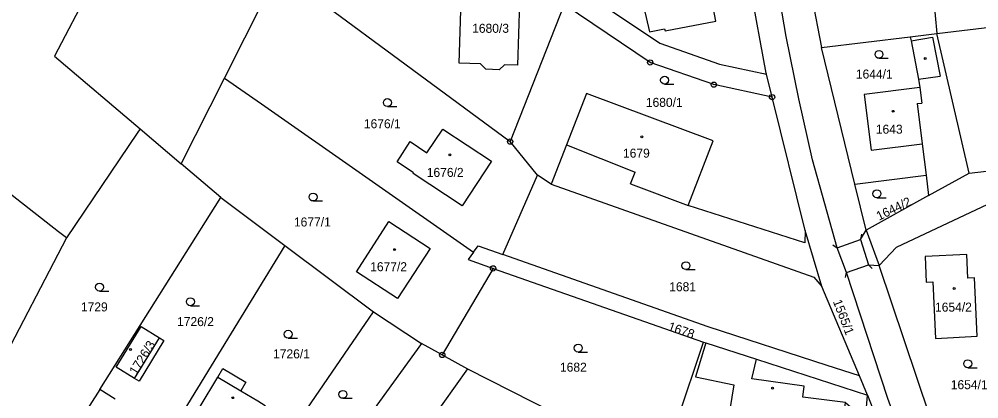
# Model space of a CAD drawing. Extents: x -562167 to -556918, y -1077891 to -1070763.
# Drawn here: x -560210.1 to -560029.1, y -1075940.9 to -1075869.3 of the extents above; entities that cross this region are included whole.
import ezdxf

# ---------------------------------------------------------------- set-up
doc = ezdxf.new("R2010")
doc.units = 0
for name, color, linetype in [('Hranice parcel', 7, 'Continuous'), ('Parcelní čísla', 7, 'Continuous'), ('Vnitřní kresba', 7, 'Continuous'), ('Značky bodu BP', 7, 'Continuous'), ('Značky budov', 7, 'Continuous'), ('Značky kultur', 7, 'Continuous')]:
    doc.layers.add(name, color=color, linetype=linetype)

msp = doc.modelspace()

# ---------------------------------------------------------------- linework, layer by layer
at = {"layer": 'Hranice parcel'}
for p, q in [((-560038.94, -1075850.52), (-560037.03, -1075871.93)), ((-560062.57, -1075854.97), (-560058.8, -1075874.61)), ((-560171.4, -1075880.35), (-560161.16, -1075860.03)), ((-560155.41, -1075864.37), (-560117.51, -1075892.34)), ((-560037.03, -1075871.93), (-560014.56, -1075869.3)), ((-560058.8, -1075874.61), (-560042.05, -1075872.55)), ((-560042.05, -1075872.55), (-560037.03, -1075871.93)), ((-560030.93, -1075898.29), (-560037.03, -1075871.93)), ((-560052.49, -1075900.39), (-560058.8, -1075874.61)), ((-560068.11, -1075883.95), (-560069.18, -1075879.62)), ((-560179.57, -1075896.55), (-560171.4, -1075880.35)), ((-560061.89, -1075909.1), (-560068.11, -1075883.95)), ((-560187.34, -1075889.94), (-560179.57, -1075896.55)), ((-560112.35, -1075898.64), (-560117.51, -1075892.34)), ((-560030.93, -1075898.29), (-560009.6, -1075895.89)), ((-560172.11, -1075902.9), (-560179.57, -1075896.55)), ((-560118.89, -1075913.64), (-560112.35, -1075898.64)), ((-560109.77, -1075900.37), (-560112.35, -1075898.64)), ((-560052.49, -1075900.39), (-560039.05, -1075898.65)), ((-560039.05, -1075898.65), (-560038.56, -1075902.52)), ((-560038.56, -1075902.52), (-560030.93, -1075898.29)), ((-560050.37, -1075909.07), (-560052.49, -1075900.39)), ((-560194.96, -1075939.09), (-560172.11, -1075902.9)), ((-560172.11, -1075902.9), (-560160.01, -1075911.93)), ((-560038.56, -1075902.52), (-560050.37, -1075909.07)), ((-560201.24, -1075910.47), (-560216.83, -1075940.47)), ((-560058.7, -1075919.66), (-560061.89, -1075909.1)), ((-560050.37, -1075909.07), (-560047.88, -1075915.74)), ((-560160.01, -1075911.93), (-560181.72, -1075947.3)), ((-560160.01, -1075911.93), (-560143.27, -1075924.43)), ((-560054.09, -1075917.01), (-560055.8, -1075912.37)), ((-560080.13, -1075927.3), (-560118.89, -1075913.64)), ((-560038.33, -1075944.12), (-560047.88, -1075915.74)), ((-560120.74, -1075916.25), (-560130.33, -1075932.58)), ((-560120.74, -1075916.25), (-560081.06, -1075930.15)), ((-560051.64, -1075936.52), (-560058.7, -1075919.66)), ((-560163.86, -1075954.36), (-560143.27, -1075924.43)), ((-560143.27, -1075924.43), (-560134.24, -1075930.44)), ((-560134.24, -1075930.44), (-560153.94, -1075957.49)), ((-560130.33, -1075932.58), (-560134.24, -1075930.44)), ((-560088.25, -1075951.75), (-560081.06, -1075930.15)), ((-560081.06, -1075930.15), (-560080.62, -1075930.29)), ((-560130.33, -1075932.58), (-560125.55, -1075935.2)), ((-560125.55, -1075935.2), (-560147.67, -1075966.13)), ((-560125.55, -1075935.2), (-560109.21, -1075943.5)), ((-560050.11, -1075940.17), (-560051.64, -1075936.52)), ((-560194.96, -1075939.09), (-560201.73, -1075949.81)), ((-560192.06, -1075940.89), (-560194.96, -1075939.09)), ((-560050.47, -1075944.82), (-560050.11, -1075940.17)), ((-560050.11, -1075940.17), (-560037.82, -1075971.43))]:
    msp.add_line(p, q, dxfattribs=at)
for points in [[(-560055.8, -1075912.37), (-560060.46, -1075895.76), (-560063.07, -1075884.26), (-560065.43, -1075872.49), (-560069.44, -1075848.98), (-560072.17, -1075831.75), (-560073.93, -1075817.46), (-560074.34, -1075808.46), (-560074.45, -1075801.18), (-560074.17, -1075792.89), (-560072.93, -1075783.94), (-560071.76, -1075777.87), (-560070.38, -1075772.61), (-560068.31, -1075767.18), (-560065.69, -1075762.57)], [(-560069.18, -1075879.62), (-560069.22, -1075879.43), (-560075.13, -1075847.2)], [(-560081.17, -1075856.82), (-560090.97, -1075858.65), (-560090.56, -1075860.6), (-560093.6, -1075861.3), (-560091.2, -1075871.65), (-560088.37, -1075871.05), (-560088.28, -1075871.44), (-560078.72, -1075869.61), (-560081.17, -1075856.82)], [(-560123.09, -1075877.68), (-560127.12, -1075877.55), (-560126.66, -1075861.57), (-560115.13, -1075861.9), (-560115.25, -1075866.12), (-560115.75, -1075866.1), (-560116.11, -1075877.91), (-560118.59, -1075877.83), (-560119.61, -1075878.8), (-560122.13, -1075878.7), (-560123.09, -1075877.68)], [(-560108.49, -1075860.9), (-560089.3, -1075873.8), (-560078.02, -1075877.75), (-560069.18, -1075879.62)], [(-560196.78, -1075863.31), (-560203.48, -1075876.2), (-560187.34, -1075889.94)], [(-560068.11, -1075883.95), (-560079.09, -1075881.6), (-560091.1, -1075877.41), (-560107.34, -1075866.47), (-560117.51, -1075892.34)], [(-560042.05, -1075872.55), (-560041.89, -1075873.36), (-560040.48, -1075880.57), (-560040.23, -1075882.16), (-560050.7, -1075883.43), (-560049.43, -1075893.93), (-560039.8, -1075892.76), (-560039.05, -1075898.65)], [(-560171.4, -1075880.35), (-560164.43, -1075885.2), (-560124.46, -1075913.2)], [(-560061.89, -1075909.1), (-560061.94, -1075911.44), (-560083.92, -1075904.4), (-560079.19, -1075892.18), (-560103.09, -1075883.29), (-560106.86, -1075892.92), (-560109.77, -1075900.37)], [(-560187.34, -1075889.94), (-560187.91, -1075890.78), (-560201.24, -1075910.47)], [(-560121.04, -1075896.04), (-560126.58, -1075904.47), (-560135.84, -1075898.38), (-560135.73, -1075898.21), (-560138.81, -1075896.15), (-560136.37, -1075892.35), (-560133.22, -1075894.47), (-560130.22, -1075890.02), (-560121.04, -1075896.04)], [(-560201.24, -1075910.47), (-560202.7, -1075909.33), (-560224.91, -1075892)], [(-560109.77, -1075900.37), (-560060.23, -1075917.93), (-560058.7, -1075919.66)], [(-560047.88, -1075915.74), (-560044.64, -1075912.25), (-560026.31, -1075903.66)], [(-560140.38, -1075907.43), (-560132.62, -1075912.49), (-560138.76, -1075921.91), (-560146.49, -1075916.9), (-560140.38, -1075907.43)], [(-560124.46, -1075913.2), (-560123.58, -1075911.98), (-560118.89, -1075913.64)], [(-560124.46, -1075913.2), (-560125.46, -1075914.6), (-560120.74, -1075916.25)], [(-560031.39, -1075913.61), (-560039.24, -1075914.03), (-560039.04, -1075918.85), (-560037.76, -1075918.8), (-560037.3, -1075929.47), (-560029.44, -1075929.03), (-560029.94, -1075918.01), (-560031.17, -1075918.09), (-560031.39, -1075913.61)], [(-560034.28, -1076097.89), (-560030.13, -1076040.04), (-560029.83, -1076034), (-560029.98, -1076027.95), (-560033.68, -1075983.37), (-560034.44, -1075977.55), (-560036.67, -1075967.75), (-560038.58, -1075961.71), (-560046.27, -1075940.8), (-560054.09, -1075917.01)], [(-560183.69, -1075929.36), (-560182.84, -1075929.86), (-560187.53, -1075937.5), (-560188.36, -1075937), (-560191.85, -1075934.91), (-560187.16, -1075927.21), (-560183.69, -1075929.36)], [(-560051.64, -1075936.52), (-560057.69, -1075934.56), (-560080.13, -1075927.3)], [(-560080.62, -1075930.29), (-560082.56, -1075936.71), (-560075.34, -1075938.19), (-560076.08, -1075942.89), (-560062.76, -1075944.73), (-560063.29, -1075949.12), (-560055.25, -1075950.14), (-560054.22, -1075941.55), (-560050.47, -1075944.82)], [(-560080.62, -1075930.29), (-560071.07, -1075933.38), (-560050.11, -1075940.17)], [(-560172.69, -1075936.75), (-560171.7, -1075935.15), (-560167.4, -1075937.73), (-560168.36, -1075939.32), (-560165.12, -1075941.24), (-560163.74, -1075942.1), (-560167.02, -1075947.62), (-560168.41, -1075946.79), (-560170.15, -1075949.83), (-560177.78, -1075945.28), (-560176.01, -1075942.31), (-560172.69, -1075936.75)]]:
    msp.add_lwpolyline(points, dxfattribs=at)
at = {"layer": 'Vnitřní kresba'}
for p, q in [((-560041.89, -1075873.36), (-560037.82, -1075872.65)), ((-560037.82, -1075872.65), (-560036.42, -1075879.97)), ((-560040.48, -1075880.57), (-560036.42, -1075879.97)), ((-560040.23, -1075882.16), (-560039.88, -1075885.06)), ((-560040.76, -1075885.17), (-560039.88, -1075885.06)), ((-560040.76, -1075885.17), (-560039.8, -1075892.76)), ((-560106.86, -1075892.92), (-560093.96, -1075898.11)), ((-560094.79, -1075900.32), (-560093.96, -1075898.11)), ((-560094.79, -1075900.32), (-560083.92, -1075904.4)), ((-560051.4, -1075910.78), (-560050.37, -1075909.07)), ((-560051.21, -1075909.8), (-560051.4, -1075910.78)), ((-560056.65, -1075911.84), (-560055.8, -1075912.37)), ((-560055.8, -1075912.37), (-560051.4, -1075910.78)), ((-560051.4, -1075910.78), (-560049.91, -1075915.59)), ((-560054.09, -1075917.01), (-560049.91, -1075915.59)), ((-560049.91, -1075915.59), (-560047.88, -1075915.74)), ((-560049.19, -1075916.28), (-560049.91, -1075915.59)), ((-560054.26, -1075918), (-560054.09, -1075917.01)), ((-560188.36, -1075937), (-560183.69, -1075929.36)), ((-560071.9, -1075937.11), (-560071.07, -1075933.38)), ((-560172.69, -1075936.75), (-560168.36, -1075939.32)), ((-560062.06, -1075938.46), (-560071.9, -1075937.11)), ((-560062.28, -1075940.54), (-560062.06, -1075938.46)), ((-560054.22, -1075941.55), (-560062.28, -1075940.54))]:
    msp.add_line(p, q, dxfattribs=at)
at = {"layer": 'Značky bodu BP'}
for centre, radius in [((-560091.1, -1075877.41), 0.5), ((-560091.1, -1075877.41), 0.0303), ((-560079.09, -1075881.6), 0.5), ((-560079.09, -1075881.6), 0.0303), ((-560068.11, -1075883.95), 0.5), ((-560068.11, -1075883.95), 0.0303), ((-560117.51, -1075892.34), 0.5), ((-560117.51, -1075892.34), 0.0303), ((-560120.74, -1075916.25), 0.5), ((-560120.74, -1075916.25), 0.0303), ((-560130.33, -1075932.58), 0.5), ((-560130.33, -1075932.58), 0.0303)]:
    msp.add_circle(centre, radius, dxfattribs=at)
at = {"layer": 'Značky budov'}
for centre in [(-560039.2, -1075876.65), (-560045.24, -1075886.62), (-560092.68, -1075891.45), (-560128.88, -1075894.84), (-560139.32, -1075912.72), (-560033.75, -1075920.06), (-560189.13, -1075931.57), (-560068, -1075938.86), (-560169.86, -1075940.64)]:
    msp.add_circle(centre, 0.175, dxfattribs=at)
at = {"layer": 'Značky kultur'}
for p, q in [((-560047.93, -1075876.63), (-560046.18, -1075876.63)), ((-560088.38, -1075881.5), (-560086.63, -1075881.5)), ((-560140.67, -1075885.73), (-560138.92, -1075885.73)), ((-560048.33, -1075902.93), (-560046.58, -1075902.93)), ((-560154.69, -1075903.54), (-560152.94, -1075903.54)), ((-560084.36, -1075916.49), (-560082.61, -1075916.49)), ((-560194.99, -1075920.54), (-560193.24, -1075920.54)), ((-560177.85, -1075923.29), (-560176.1, -1075923.29)), ((-560159.4, -1075929.42), (-560157.65, -1075929.42)), ((-560104.68, -1075932.04), (-560102.93, -1075932.04)), ((-560031.19, -1075934.99), (-560029.44, -1075934.99)), ((-560149.08, -1075940.76), (-560147.33, -1075940.76))]:
    msp.add_line(p, q, dxfattribs=at)
for centre in [(-560047.93, -1075875.88), (-560088.38, -1075880.75), (-560140.67, -1075884.98), (-560048.33, -1075902.18), (-560154.69, -1075902.79), (-560084.36, -1075915.74), (-560194.99, -1075919.79), (-560177.85, -1075922.54), (-560159.4, -1075928.67), (-560104.68, -1075931.29), (-560031.19, -1075934.24), (-560149.08, -1075940.01)]:
    msp.add_circle(centre, 0.75, dxfattribs=at)

# ---------------------------------------------------------------- texts
at = {"layer": 'Parcelní čísla'}
for s, p in [('1680/3', (-560124.69, -1075871.82)), ('1644/1', (-560052.3, -1075880.45)), ('1680/1', (-560091.92, -1075885.79)), ('1676/1', (-560145.12, -1075889.82)), ('1643', (-560048.53, -1075890.85)), ('1679', (-560096.23, -1075895.37)), ('1676/2', (-560133.25, -1075899)), ('1677/1', (-560158.31, -1075908.35)), ('1677/2', (-560143.93, -1075916.79)), ('1681', (-560087.51, -1075920.57)), ('1729', (-560198.5, -1075924.37)), ('1654/2', (-560037.36, -1075924.41)), ('1726/2', (-560180.36, -1075927.14)), ('1726/1', (-560162.25, -1075933.22)), ('1682', (-560108.12, -1075935.74)), ('1654/1', (-560034.39, -1075939.04))]:
    msp.add_text(s, height=1.7, dxfattribs=at).set_placement(p)
for s, rotation, p in [('1644/2', 26, (-560047.92, -1075907.28)), ('1565/1', 291, (-560056.65, -1075922.49)), ('1678', 341, (-560087.88, -1075927.91)), ('1726/3', 58, (-560188.07, -1075936.47))]:
    msp.add_text(s, height=1.7, rotation=rotation, dxfattribs=at).set_placement(p)

doc.saveas('drawing.dxf')
